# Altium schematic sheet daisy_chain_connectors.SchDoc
size A3; DocumentNumber: 12; SheetNumber: 12; SheetTotal: 15; SheetDescription: Daisy Chain Connectors
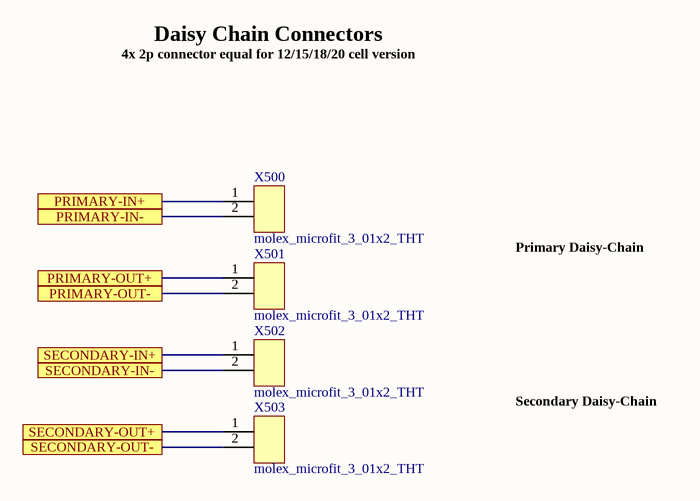
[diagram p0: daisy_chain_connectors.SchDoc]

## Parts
X500  molex_microfit_3_01x2_THT  [MOLEX_MICROFIT_01x2_THT]
X501  molex_microfit_3_01x2_THT  [MOLEX_MICROFIT_01x2_THT]
X502  molex_microfit_3_01x2_THT  [MOLEX_MICROFIT_01x2_THT]
X503  molex_microfit_3_01x2_THT  [MOLEX_MICROFIT_01x2_THT]

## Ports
PRIMARY-IN+, PRIMARY-IN-, PRIMARY-OUT+, PRIMARY-OUT-, SECONDARY-IN+, SECONDARY-IN-, SECONDARY-OUT+, SECONDARY-OUT-

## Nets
PRIMARY-IN+: X500.1 ; port PRIMARY-IN+
PRIMARY-IN-: X500.2 ; port PRIMARY-IN-
PRIMARY-OUT+: X501.1 ; port PRIMARY-OUT+
PRIMARY-OUT-: X501.2 ; port PRIMARY-OUT-
SECONDARY-IN+: X502.1 ; port SECONDARY-IN+
SECONDARY-IN-: X502.2 ; port SECONDARY-IN-
SECONDARY-OUT+: X503.1 ; port SECONDARY-OUT+
SECONDARY-OUT-: X503.2 ; port SECONDARY-OUT-

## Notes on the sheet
- Daisy Chain Connectors
- 4x 2p connector equal for 12/15/18/20 cell version
- Primary Daisy-Chain
- Secondary Daisy-Chain

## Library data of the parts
X500-X503 = molex_microfit_3_01x2_THT: Micro-Fit 3.0 Right Angle Header, 3.00mm Pitch, Dual Row, 2 Circuits, with Snap-in Plastic Peg PCB Lock, Tin, Glow Wire Capable, Black, 43045-0200; Manufacturer: Molex; Circuits: 2; Rated Voltage: 600V; Rated Current: 8.5A; Automotive Qualified: False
